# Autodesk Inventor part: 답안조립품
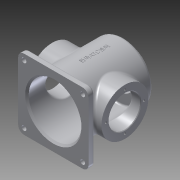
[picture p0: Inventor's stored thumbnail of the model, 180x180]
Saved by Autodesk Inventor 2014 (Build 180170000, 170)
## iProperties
Created: 2015-10
Part Number: 답안조립품
Material: 알루미늄 6061
Document SubType Name: Modeling
Designer: aapexcom
Density: 2.71 g/cm^3
Appearance: 알루미늄 - 평지
Mass: 987.646 g
Surface Area: 1042.56 cm^2
Volume: 364.445 cm^3
Author: aapexcom
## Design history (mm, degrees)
sketch "스케치1"
  geometry: L1 (0, 0)-(120, 0); L2 (120, 0)-(120, 120); L3 (120, 120)-(0, 120); L4 (0, 120)-(0, 0); 4 further points
  constraints: 8 end point, 2 midpoint, 2 parallel, 1 horizontal, 1 horizontal alignment, 1 perpendicular, 1 vertical alignment
  dimensions: "d0" = 120 distance of L2.end L3.end; "d1" = 120 distance of L1.end L2.end; "d2" = 10 distance from line of L4 point (10, 110); "d3" = 10 distance from line of L3 point (10, 110)
extrude "돌출1" new body sketch "스케치1" distance "d6" = 10; taper "d7" = 0 deg
sketch "스케치2"
  geometry: C1 r 50 at (-60, -60); 1 further point
  constraints: 1 centre point, 1 coincident
  dimensions: "d8" = 100 diameter of C1
extrude "돌출2" join sketch "스케치2" distance "d9" = 110; taper "d10" = 0 deg
hole "구멍1" sketch "스케치1" diameter "d11" = 8; stored, may be unused: countersink angle "d15" = 90 deg, drill point angle "d17" = 118 deg; dims "d12" = 6, "d13" = 4, "d14" = 2, "d16" = 8
sketch "스케치3"
  geometry: C1 r 50 at (0, 0) reference; C2 r 40 at (0, 0); 1 further point
  constraints: 1 centre point, 1 coincident
  dimensions: "d24" = 80 diameter of C2
extrude "돌출3" join sketch "스케치3" distance "d25" = 5; taper "d26" = 0 deg
hole "구멍2" sketch "스케치1" diameter "d27" = 54; stored, may be unused: countersink angle "d31" = 90 deg, drill point angle "d33" = 118 deg; dims "d28" = 6, "d29" = 90, "d30" = 112, "d32" = 8
sketch "스케치4"
  geometry: L1 (0, 0)-(0, 35.447); L2 (0, 0)-(-22.981, 22.981); C1 r 40 at (0, 0) reference; 2 further points
  constraints: 4 end point, 1 coincident, 1 vertical
  dimensions: "d34" = 32.5 distance of L1.start L2.end; "d35" = 45 deg angle of L1 L2
hole "구멍3" sketch "스케치4" at (-22.981, 22.981) diameter "d36" = 3.242; stored, may be unused: countersink angle "d40" = 90 deg, drill point angle "d42" = 118 deg; dims "d37" = 8, "d38" = 90, "d39" = 112, "d41" = 10
node "작업 평면2"
  node "작업 평면1"
sketch "스케치5"
  geometry: L1 (0, 0)-(120, 0) reference; C1 r 40 at (60, 60); 1 further point
  constraints: 1 centre point, 1 midpoint, 1 vertical alignment
  dimensions: "d47" = 60 distance from line of C1.centre L1; "d48" = 80 diameter of C1
extrude "돌출4" join sketch "스케치5" stored distance "d49" = 5; taper "d50" = 0 deg
sketch "스케치6"
  geometry: L1 (0, 0)-(0, 32.5); C1 r 40 at (0, 0) reference; 2 further points
  constraints: 2 end point, 1 coincident, 1 vertical
  dimensions: "d79" = 32.5 distance of L1.start L1.end
hole "구멍4" sketch "스케치6" at (0, 32.5) diameter "d53" = 3.242; stored, may be unused: countersink angle "d57" = 90 deg, drill point angle "d59" = 118 deg; dims "d54" = 8, "d55" = 90, "d56" = 112, "d58" = 10
sketch "스케치7"
  geometry: C1 r 40 at (0, 0) reference; 2 further points
  constraints: 1 coincident
hole "구멍5" sketch "스케치7" at (0, 0) diameter "d63" = 54; stored, may be unused: countersink angle "d67" = 90 deg, drill point angle "d69" = 118 deg; dims "d64" = 8, "d65" = 90, "d66" = 112, "d68" = 10
fillet "모깎기1" dims "d70" = 10
fillet "모깎기2" dims "d71" = 5
fillet "모깎기3" dims "d72" = 3
chamfer "모따기1" distance "d73" = 3; stored, may be unused: second distance "d74" = 2, angle "d75" = 45 deg
node "작업 평면3"
sketch "스케치8"
  geometry: L1 (-50, -10)-(50, -10) reference; 4 further points
  constraints: 2 midpoint, 1 vertical alignment, 1 other
  dimensions: "d76" = 70 distance from line of L1 point (0, 60)
feature "엠보싱1" sketch "스케치8" dims "d0" = 120, "d1" = 120, "d2" = 10, "d3" = 10, "d77" = 0.5, "d78" = 0
chamfer "모따기2" distance "d80" = 1; stored, may be unused: second distance "d81" = 2, angle "d82" = 45 deg
fillet "모깎기4" dims "d83" = 3
node "솔리드1"
pattern_linear "직사각형 패턴1" dims "d20" = 100
pattern_circular "원형 패턴1" dims angle "d44" = 360 deg
pattern_circular "원형 패턴2" dims angle "d61" = 360 deg
mirror "대칭1"
other parameters: "d46" = 62
